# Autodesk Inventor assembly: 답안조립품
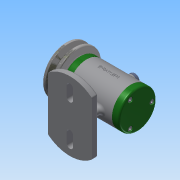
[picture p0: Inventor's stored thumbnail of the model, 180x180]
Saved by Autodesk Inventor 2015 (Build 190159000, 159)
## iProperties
Created: 2017-12
Part Number: 답안조립품
Document SubType Name: Assembly
Designer: Administrator
Author: Administrator
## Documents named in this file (14)
- C:\Users\Administrator\Desktop\471208V1029\답안조립품.iam
- C:\Users\Administrator\Desktop\471208V1029\본체.ipt
- C:\Users\Administrator\Desktop\471208V1029\V벨트풀리.ipt
- C:\Users\Administrator\Desktop\471208V1029\고무캡.ipt
- C:\Users\Administrator\Desktop\471208V1029\너트 M 8.ipt
- C:\Users\Administrator\Desktop\471208V1029\뒤커버.ipt
- C:\Users\Administrator\Desktop\471208V1029\베어링 15 x 32 x 9.ipt
- C:\Users\Administrator\Desktop\471208V1029\볼트 M4 x 12.ipt
- C:\Users\Administrator\Desktop\471208V1029\스프링와셔 8.ipt
- C:\Users\Administrator\Desktop\471208V1029\앞커버.ipt
- C:\Users\Administrator\Desktop\471208V1029\오일 실 15 25 7.ipt
- C:\Users\Administrator\Desktop\471208V1029\와셔 8x17.ipt
- C:\Users\Administrator\Desktop\471208V1029\축.ipt
- C:\Users\Administrator\Desktop\471208V1029\키 3 x 3 x 12.ipt
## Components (2 placed, 2 different names)
1. V벨트풀리:1 — 각도:1
2. 고무캡:1 — 각도:5
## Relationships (2: Angle 2)
- 각도:1 [Angle]: V벨트풀리:1
- 각도:5 [Angle]: 고무캡:1
